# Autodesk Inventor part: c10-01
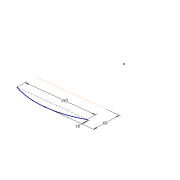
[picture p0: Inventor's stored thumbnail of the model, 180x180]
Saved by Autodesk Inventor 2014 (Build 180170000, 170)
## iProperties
Created: 2010-12
Part Number: c10-01
Material: Generic
Document SubType Name: Modeling
Designer: Thom Tremblay
Density: 1 g/cm^3
Appearance: Satin - Linen
Author: Thom Tremblay
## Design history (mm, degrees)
sketch "Sketch1"
  geometry: L1 (-60, -12)-(60, -12); L2 (60, -12)-(60, 12); L3 (60, 12)-(-60, 12); L4 (-60, 12)-(-60, -12); A1 r 350 centre (0, -332.819) between (60, 12) and (-60, 12); A2 r 350 centre (0, 332.819) between (-60, -12) and (60, -12); 3 further points
  constraints: 8 end point, 4 point on circle, 2 centre point, 2 midpoint, 2 parallel, 1 equal radius, 1 horizontal, 1 horizontal alignment, 1 perpendicular, 1 vertical alignment
  dimensions: "d0" = 120 distance of L3.end L2.end; "d1" = 24 distance of L2.end L1.end; "d2" = 350 radius of A1
workplane "Work Plane4"
sketch "Sketch2"
  geometry: L1 (-75, -16)-(75, -16); L2 (-75, -60)-(75, -60); A1 r 183.781 centre (0, -183.781) between (75, -16) and (-75, -16); 2 further points
  constraints: 4 end point, 3 point on circle, 1 centre point, 1 coincident, 1 horizontal, 1 parallel
  dimensions: "d5" = 16 distance from line of point (0, 0) L1; "d7" = 60 distance from line of point (0, 0) L2; "d55" = 150 distance of L1.start L1.end
sketch "Sketch5"
  geometry: L1 (-60, 12)-(-60, -12) reference; L2 (60, -12)-(60, 12) reference; L3 (-58, 10.314)-(-58, -10.314); L4 (58, -10.314)-(58, 10.314); A1 r 350 centre (0, 332.819) between (-60, -12) and (60, -12) reference; A2 r 350 centre (0, -332.819) between (60, 12) and (-60, 12) reference; A3 r 348 centre (0, 332.819) between (-58, -10.314) and (58, -10.314); A4 r 348 centre (0, -332.819) between (58, 10.314) and (-58, 10.314); 1 further point
  constraints: 4 end point, 4 point on circle, 2 centre point, 3 other
  dimensions: "d37" = 2 distance between parallel lines of L2 L4
sketch "Sketch6"
  geometry: L1 (-60, 0)-(60, 0); L2 (60, 0)-(58.843, 22.085); L3 (-60, 0)-(-58.779, 23.307); A1 r 691.758 centre (630.81, -36.204) between (-60, 0) and (-58, -100); A2 r 691.758 centre (-630.81, -36.204) between (58, -100) and (60, 0); 1 further point
  constraints: 6 end point, 4 point on circle, 2 centre point, 2 tangent, 1 horizontal
  dimensions: "d53" = 87 deg angle of L1 L3; "d54" = 87 deg angle of L1 L2 (= d53)
sketch "Sketch7"
  geometry: L1 (17.181, 0)-(12, 0) reference; L2 (15.181, -100)-(10.314, -100) reference; L3 (17.181, 0)-(16.768, 11.838); A1 r 911.322 centre (-893.585, -31.805) between (15.181, -100) and (17.181, 0); 1 further point
  constraints: 2 end point, 2 point on circle, 1 centre point, 1 tangent
  dimensions: "d56" = 88 deg angle of L1 L3
feature "LoftSrf2" sketch "Sketch5", "Sketch6", "Sketch7" dims "d57" = 0, "d58" = 90 deg, "d59" = 0, "d60" = 90 deg, "d61" = 0, "d62" = 90 deg, "d63" = 0, "d64" = 90 deg, "d65" = 0, "d66" = 90 deg
patch "Boundary Patch1" dims "d13" = 0, "d67" = 0, "d68" = 0, "d69" = 0, "d70" = 0
workplane "Work Plane1"
sketch "Sketch3"
  geometry: L1 (52, -85)-(52, -73); L2 (38, -73)-(38, -85); A1 r 7 centre (45, -73) between (52, -73) and (38, -73); A2 r 7 centre (45, -85) between (38, -85) and (52, -85); 1 further point
  constraints: 4 end point, 4 point on circle, 4 tangent, 2 centre point, 1 parallel, 1 vertical
  dimensions: "d15" = 12 distance of L1.start L1.end; "d16" = 7 radius of A1; "d50" = 45 horizontal distance of A1.centre point (0, 0); "d51" = 85 vertical distance of point (0, 0) A2.centre
extrude_surface "ExtrusionSrf2" sketch "Sketch3" dims "d19" = 14, "d20" = 5 deg
pattern_linear "Rectangular Pattern1" dims "d23" = 90
workplane "Work Plane2"
body "Srf3"
body "Srf4"
body "Srf5"
body "Srf6"
body "Srf7"
body "Srf11"
extrude_surface "ExtrusionSrf3"
extrude_surface "ExtrusionSrf4"
extrude_surface "ExtrusionSrf5"
other parameters: "d14" = -24, "d52" = -6
